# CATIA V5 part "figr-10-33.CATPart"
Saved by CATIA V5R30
Part number: Part1
Bounding box of the stored display mesh (mm): x -193.573 to 205.258, y -140.014 to 12.054, z -96.593 to 19.319
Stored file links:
  D:\PROJECTS\CATIA V56R 2020\Resources\Parts File\c10_catia_v5_6r2020_prt\figr-10-33.CATPart
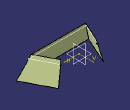
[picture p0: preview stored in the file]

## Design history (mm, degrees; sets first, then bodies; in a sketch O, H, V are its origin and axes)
Body1 (main body)
  Sketch1 on xy-plane, origin (0, 0, 0), H (1, 0, 0), V (0, 1, 0)
    line L1 (-101.4744, 0) -> (-153.3719, -114.1323)
    point P1 (-101.4744, 0)
    line L2 (-153.3719, -114.1323) -> (162.3879, -114.1323)
    line L3 (162.3879, -114.1323) -> (102.3183, 0)
    point P4 (102.3183, 0)
    coincidence: P1 H, P4 H
    horizontal: L2 H
  Sweep1: type Segment, GuideCrv Sketch1, Length1 20, Length2 100, Angle 15, DraftDirection xy-plane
